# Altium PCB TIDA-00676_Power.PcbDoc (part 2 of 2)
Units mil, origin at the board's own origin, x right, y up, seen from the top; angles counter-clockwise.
Board outline 5000 x 3510 mil, 2 copper layers (Top Layer, Bottom Layer), stack 40 mil thick; 88 components, 29 nets, 205 pads, 45 vias.
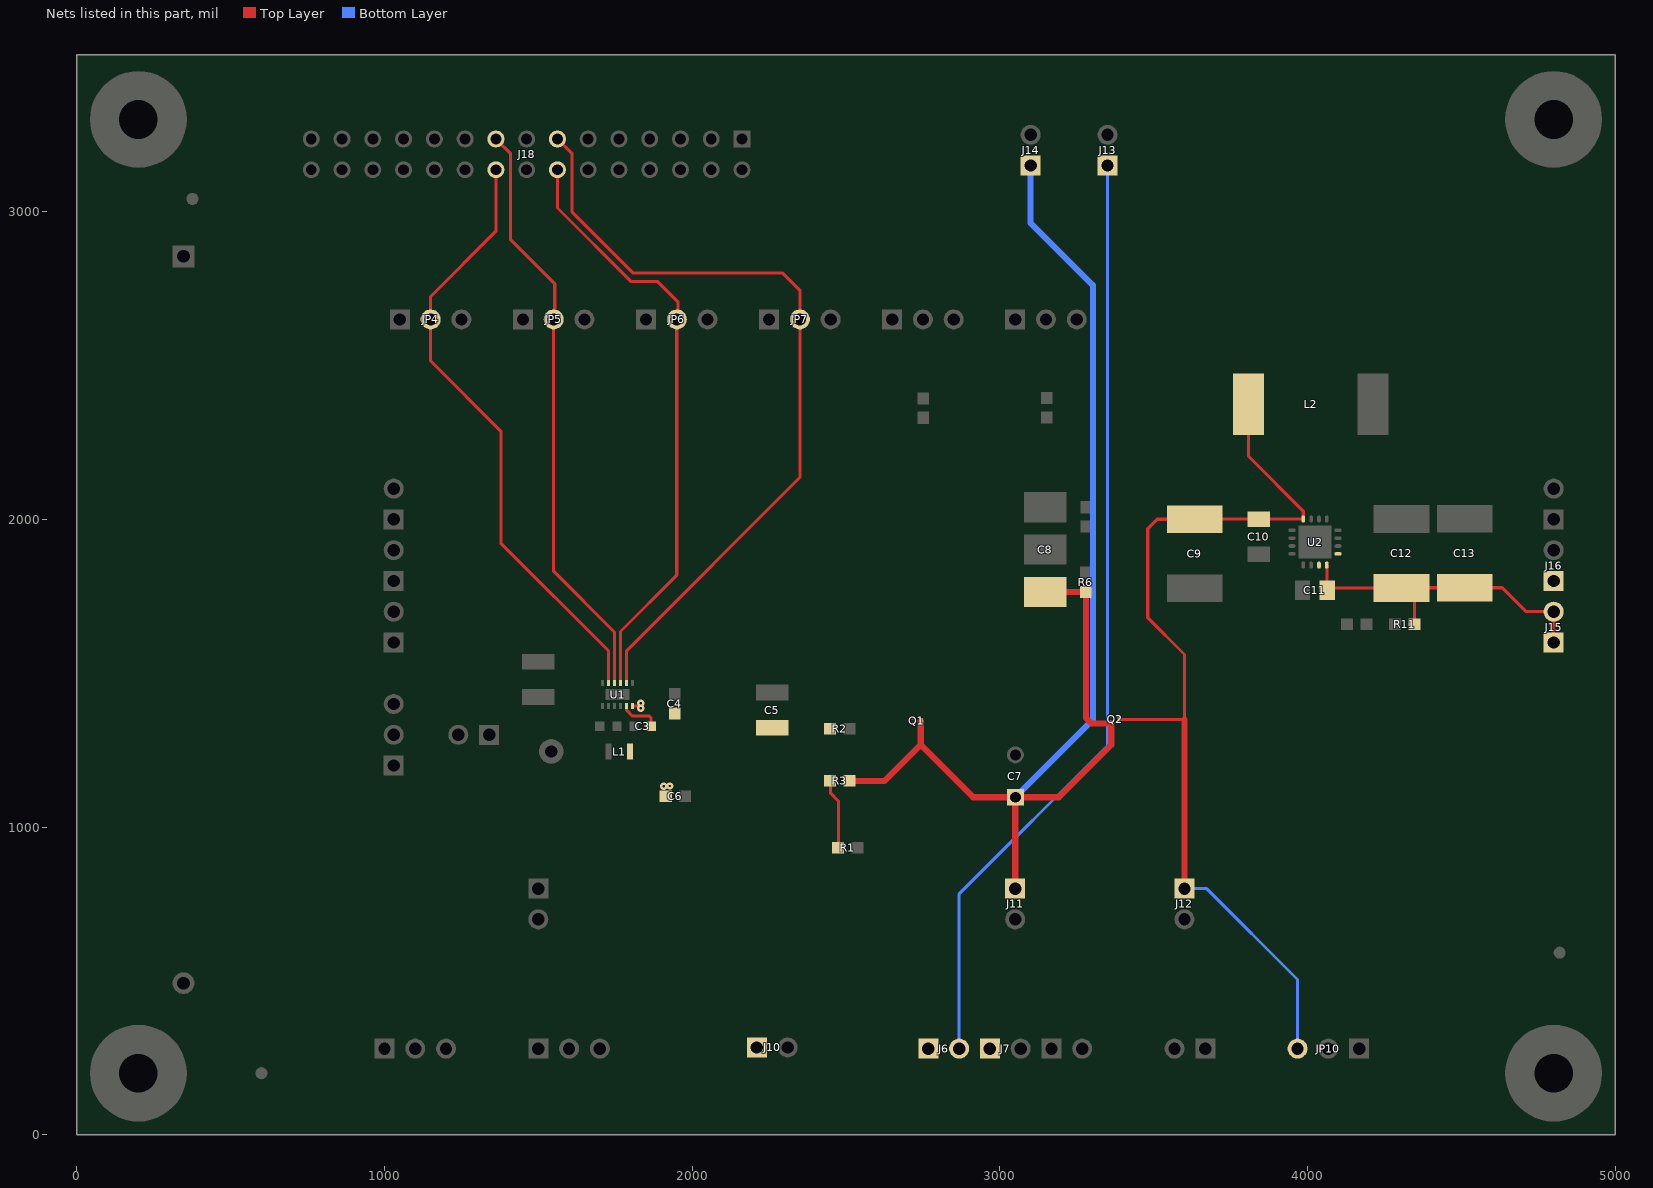
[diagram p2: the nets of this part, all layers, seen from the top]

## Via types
v1: diameter 24, hole 8, Top Layer to Bottom Layer, tented both sides, 34 vias
v2: diameter 19.68, hole 7.87, Top Layer to Bottom Layer, 5 vias
v3: diameter 19.68, hole 7.87, Top Layer to Bottom Layer, tented both sides, 4 vias
v4: diameter 34, hole 16, Top Layer to Bottom Layer, 2 vias

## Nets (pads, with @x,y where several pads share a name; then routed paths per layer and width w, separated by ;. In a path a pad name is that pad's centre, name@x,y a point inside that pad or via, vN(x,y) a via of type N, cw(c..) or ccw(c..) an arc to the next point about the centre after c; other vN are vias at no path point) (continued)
VIN_BOOST: C9.1 C10.1 J12.1 JP10.3 L2.1 Q2.3 U2.8 | length 3111.1
  Top Layer w10: Q2.3@3387.8,1350 3600,1350 3600,1561.17 3480.79,1680.37 3480.79,1969.91 3511.44,2000.56 C9.1@3633.89,2000.56 3634.18,2000.85 C10.1@3841.31,2000.85 3841.57,2001.11 U2.8@3986.05,2001.11 3986.05,2026.7 3808.56,2204.18 L2.1@3808.56,2374.34
  Top Layer w20: J12.1@3600,800 3600,1350
  Bottom Layer w10: J12.1@3600,800 3672.27,800 3967.7,504.57 JP10.3@3967.7,280
VLOAD: C6.1 J10.1 U1.6 | length 48.8
  Top Layer w10: U1.6@1806.59,1393 1822.57,1393 1832.37,1383.2 1832.37,1398.7 1832.67,1399 1832.36,1399.31 v1@1832.36,1401.86
  other v1: 1907.34,1133.06 1927.22,1133.52 1832.37,1386.2 1832.36,1402.86
VOUT_BOOST: C11.1 C12.1 C13.1 J15.1 J15.2 J16.1 R11.2 U2.1 U2.15 U2.16 | length 1088.9
  Top Layer w10: U2.16@4062.82,1851.5 4062.82,1771.09 C11.1@4063.64,1770.26 4070.66,1777.27 C12.1@4305.78,1777.27 ; R11.2@4347.25,1658.86 4347.25,1735.8 C12.1@4305.78,1777.27 ; J15.1@4800,1600 J15.2@4800,1700 4710.49,1700 4632.66,1777.83 C13.1@4511.08,1777.83 4306.34,1777.83 C12.1@4305.78,1777.27
VOUT_BUCK: C3.1 C4.1 C5.1 J6.1 J6.2 J7.1 J13.1 L1.2 R1.2 R2.1 R3.1 U1.5 | length 3434.7
  Top Layer w10: U1.5@1786.9,1393 1786.9,1379.6 1805.98,1360.52 1809.06,1360.52 ; 1809.09,1360.49 1860.44,1360.49 1866.67,1354.26 C3.1@1866.67,1327.5 ; R3.1@2448.5,1150 2450,1148.5 2450,1110 2475,1085 R1.2@2475,926.5
  Bottom Layer w10: J6.2@2867.7,280 2867.7,782.84 3350,1265.14 J13.1@3350,3150
VSEL1: J18.18 JP4.2 U1.11 | length 1995.8
  Top Layer w10: J18.18@1362.1,3136.38 1362.1,2936.54 1150,2724.44 JP4.2@1150,2650 1150,2515 1378.39,2286.61 1378.39,1922.31 1727.84,1572.86 U1.11@1727.84,1467.8
VSEL2: J18.17 JP5.2 U1.10 | length 1931
  Top Layer w10: J18.17@1362.1,3236.38 1410,3188.48 1410,2908.74 1553.3,2765.44 1553.3,2653.3 JP5.2@1550,2650 1550,1831.26 1747.53,1633.73 U1.10@1747.53,1467.8
VSEL3: J18.14 JP6.2 U1.9 | length 1958.5
  Top Layer w10: J18.14@1562.1,3136.38 1562.1,3012.11 1800.35,2773.86 1887.05,2773.86 1953.3,2707.61 1953.3,2653.3 JP6.2@1950,2650 1950,1818.7 1767.21,1635.92 U1.9@1767.21,1467.8
VSEL4: J18.13 JP7.2 U1.8 | length 2613.3
  Top Layer w10: J18.13@1562.1,3236.38 1610,3188.48 1610,2998.34 1808.12,2800.22 2294.78,2800.22 2350,2745 JP7.2@2350,2650 2350,2135.93 1786.9,1572.83 U1.8@1786.9,1467.8
VSUPER-CAP: C7.1 C8.1 J11.1 J14.1 Q1.3 Q2.2 R3.2 R6.2 | length 4356.7
  Top Layer w20: R3.2@2511.5,1150 2625.44,1150 2742.8,1267.36 ; Q1.3@2742.8,1345 2742.8,1267.36 ; J11.1@3050,800 3050,1096.46 C7.1@3050.43,1096.89 ; C8.1@3148.12,1764.3 3148.35,1764.07 R6.2@3279.85,1764.07 3279.85,1355.41 3298.92,1336.34 3362.2,1336.34 3362.2,1266.81 3192.28,1096.89 C7.1@3050.43,1096.89 ; 2742.8,1267.36 2913.26,1096.89 C7.1@3050.43,1096.89
  Bottom Layer w20: C7.1@3050.43,1096.89 3302.48,1348.94 3302.48,2760.86 3100,2963.35 J14.1@3100,3150
pads on no net: FID1.1 FID2.1 FID3.1 H1.1 H2.1 H3.1 H4.1 H5.0 H6.0 H7.0 H8.0 J18.1 J18.2 J18.3 J18.5 J18.7 J18.9 J18.10 J18.21 J18.22 J18.29 J18.30 LBL1.0 SH-JP1.0 SH-JP2.0 SH-JP3.0 SH-JP4.0 SH-JP5.0 SH-JP6.0 SH-JP7.0 SH-JP8.0 SH-JP9.0 SH-JP10.0 SH-JP11.0 U2.2 U2.9 U2.12

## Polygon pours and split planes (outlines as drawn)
GND on Bottom Layer "GND-Flood_BOT" (solid, remove dead copper, pour order 30): 50,3450 4948.63,3450 4948.63,50 50,50
VLOAD on Bottom Layer "Bottom Layer-No Net" (solid, pour order 29): 1817.38,1408.72 1817.38,1195.81 1898.86,1114.34 1934.51,1114.34 1945,1124.83 1945,1335 1945,1340 1865,1420 1860.42,1424.58 1830,1424.58 1820.45,1424.58 1816.43,1420.56
VIN_BOOST on Top Layer "Top Layer-No Net 1" (solid, remove dead copper, pour order 18): 3381.98,1330.78 3399.16,1313.6 3491.18,1313.6 3515.71,1313.6 3555.8,1273.51 3555.8,810.65 3555.8,757.37 3564.76,748.41 3565.29,747.88 3627.01,747.88 3645.73,747.88 3652.06,754.21 3652.06,1663.31 3620.45,1694.92 3545.5,1694.92 3509.01,1731.41 3509.01,1896.78 3545.5,1933.28 3652.06,1933.28 3854.66,1933.28 3891.93,1970.55 3908.99,1987.61 3989.39,1987.61 3997.02,1995.24 3997.02,2490.67 3981.39,2506.31 3755.29,2506.31 3644.2,2506.31 3528.2,2390.31 3440.71,2302.82 3440.71,2006.92 3440.71,1441.06 3388.32,1388.67 3381.98,1382.33
VOUT_BOOST on Top Layer "Top Layer-No Net" (solid, remove dead copper, pour order 16): 4026,1856.58 4026,1727.63 4031.35,1722.28 4038.16,1715.46 4155.92,1715.46 4483.87,1715.46 4627.77,1571.56 4673.54,1525.79 4803.21,1525.79 4853.33,1525.79 4864.23,1536.69 4881.66,1554.13 4881.66,1589 4881.66,1819.43 4844.81,1856.29 4698.06,1856.29 4661.24,1893.12 4087.54,1893.12 4087.54,1872.71 4078.19,1863.36 4032.79,1863.36
GND on Top Layer "GND-Flood_TOP" (solid, remove dead copper, pour order 28): 50,3450 4948.63,3450 4948.63,50 50,50
NetC8_3 on Top Layer "Top Layer-NetC8_3" (solid, pour order 19): 3078.76,1851.88 3105.14,1825.51 3234.91,1825.51 3252.37,1808.05 3301.47,1808.05 3302.34,1807.18 3313.72,1818.57 3313.72,1984.29 3302.02,1995.99 3258.81,1995.81 3235.61,1971.47 3096.64,1971.47 3078.76,1953.6
VSUPER-CAP on Top Layer "Top Layer-VSUPER_CAP" (solid, pour order 22): 2490.14,1104.93 2552.84,1042.24 3283.05,1042.24 3366.97,1126.16 3366.97,1345.93 3347.64,1345.88 3336.73,1357.21 3336.73,1783.26 3329.17,1789.13 3245.64,1789.13 3218.35,1814.73 3077.32,1814.74 3009.36,1748.9 3008.62,1628.1 2732.29,1350.12 2732.3,1277.68 2683.66,1229.03 2506.45,1229.03 2490.14,1212.72
VLOAD on Top Layer "Keep-Out Layer-VLOAD" (solid, pour order 17): 1816.34,1402.79 1827.85,1414.29 1837.35,1414.29 1845.05,1406.59 1845.05,1378.77 1840.33,1374.04 1838.91,1372.62 1833.39,1372.62 1825.56,1372.62 1818.68,1379.51 1815.03,1383.15 1801.79,1383.15 1801.79,1402.79
NetQ1_2 on Top Layer "Top Layer-NetQ1_2" (solid, pour order 20): 2490.59,1251.96 2502.91,1239.64 2674.66,1239.64 2725.7,1290.68 2725.66,1341.11 2704.84,1341.11 2697.63,1345.65 2494.14,1345.63 2494.14,1345.38 2490.59,1341.83
Q2_CTRL on Top Layer "Top Layer-Net_Q2_CTRL" (solid, pour order 23): 3367.31,1353.88 3372.13,1358.7 3372.13,1406.9 3352.68,1406.9 3352.16,1407.41 3352.16,1358.53 3356.81,1353.88
Q1_CTRL on Top Layer "Top Layer-Net_Q1_CTRL" (solid, pour order 21): 2722.33,1348.72 2722.33,1355.1 2748.09,1380.86 2734.46,1394.5 2707.28,1367.32 2707.28,1351.43 2710.06,1348.66 2722.27,1348.66
VBAT on Top Layer "Top Layer-VBAT" (solid, pour order 27): 1075,1355 1100,1380 1100,1830 1080,1850 820,1850 700,1970 700,2826.45 571.45,2955 271.29,2955 150,2833.7 150,1715 510,1355
VIN on Top Layer "Top Layer-VIN" (solid, pour order 26): 1305,1240 1305,1246.4 1286.4,1265 1286.4,1359.7 1286.4,1406.4 1340,1460 1600,1460 1620,1460 1670,1410 1673.22,1406.78 1705.07,1406.78 1713.08,1406.78 1715,1404.86 1715,1370 1715,1295 1710,1290 1675,1255 1495,1255 1480,1240
VLOAD on Top Layer "Top Layer-VLOAD" (solid, pour order 25): 2252.77,233.03 2224.74,205 1946.77,205 1921.3,230.47 1921.3,681.01 1780,822.31 1780,1130 1804.43,1154.43 1930.57,1154.43 1947.67,1137.33 1947.67,987.33 2252.77,682.23
VOUT_BUCK on Top Layer "Top Layer-VOUT_BUCK" (solid, pour order 24): 1850.83,1388.5 1850.83,1376.72 1797.06,1376.72 1791.89,1381.89 1791.89,1402.31 1781.93,1402.31 1781.93,1377.86 1806.46,1353.33 1827.44,1353.33 1831.3,1349.47 1831.3,1296.3 1825,1290 1785,1290 1780,1285 1780,1210 1798.87,1191.13 2073.87,1191.13 2206.37,1058.63 2206.37,881.83 2382.25,705.94 2382.25,504.82 2675.71,211.36 2997.75,211.36 3012.86,226.47 3012.86,440.85 2593.59,860.12 2536.43,860.12 2505.81,890.74 2505.81,1069.71 2475,1105 2475,1340 2420,1395 1851.89,1395

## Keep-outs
Keep-Out Layer:
  lines w10: -5,0 ccw(c0,0) 0,-5 ; -5,0 ccw(c0,0) 0,-5 ; -5,0 -5,3510 ; -5,3510 cw(c0,3510) 0,3515 ; -5,3510 cw(c0,3510) 0,3515 ; 0,-5 5000,-5 ; 0,3515 5000,3515 ; 5000,-5 ccw(c5000,0) 5005,0 ; 5000,-5 ccw(c5000,0) 5005,0 ; 5000,3515 cw(c5000,3510) 5005,3510 ; 5000,3515 cw(c5000,3510) 5005,3510 ; 5005,0 5005,3510
  text ".Layer_Name" at 577,-858.49 h60

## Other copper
Top Layer:
  text ".Layer_Name" at 577,-858.49 h60
Bottom Layer:
  text ".Layer_Name" at 577,-858.49 h60

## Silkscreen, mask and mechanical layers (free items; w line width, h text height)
Top Overlay:
  circle w10: c1970.69,1611.9 r5.1
  lines w10: 1200,1230 1360,1230 ; 1345,1220 1360,1230 ; 1345,1240 1360,1230 ; 1946.21,1592.35 2076.21,1592.35 2076.21,1685.27 1946.21,1685.27 1946.21,1592.35
  text "ADC1" at 3025,3005 h40
  text "ADC0" at 3280,3000 h40
  text ".PRJ_Title" at 3615,2968.1 h60
  text ".PCB_Rev" at 3852.96,2864.64 h60
  text "REV." at 3618.91,2861.81 h60
  text "LOW" at 3209.97,2537.46 h40
  text "LOW" at 1607.17,2534.07 h40
  text "LOW" at 2004.48,2534.07 h40
  text "HIGH" at 1364.57,2532.9 h40
  text "LOW" at 1204.01,2531.72 h40
  text "HIGH" at 956.72,2530.55 h40
  text "HIGH" at 1764.22,2530.55 h40
  text "LOW" at 2402.95,2530.55 h40
  text "HIGH" at 2982.68,2531.47 h40
  text "HIGH" at 2560,2530 h40
  text "LOW" at 2815,2530 h40
  text "HIGH" at 2161.52,2528.21 h40
  text "VSEL2" at 1458.33,2475.47 h40
  text "VSEL1" at 1064.55,2473.12 h40
  text "VSEL3" at 1863.84,2471.95 h40
  text "VSEL4" at 2265.82,2470.77 h40
  text "Q1 CTRL" at 2640,2470 h40
  text "Q2 CTRL" at 3034.52,2469.66 h40
  text "GND" at 4731.03,1969.15 h40 r90
  text "GND" at 1160,1945 h40 r90
  text "U1" at 1992.72,1626.73 h40
  text "VBOOST" at 4731.03,1579.15 h40 r90
  text "RF AMP SUPPLY" at 4664.28,1575.97 h40 r90
  text "VIN_BAT" at 1170,1560 h40 r90
  text "1" at 1961.52,1530.9 h39.37
  text "VIN_BAT" at 699.85,1396.07 h40
  text "VIN" at 845,1280 h40
  text "3V3_REF" at 699.85,1186.07 h40
  text "I_IN" at 1215,1158 h40
  text "TP" at 1465,595 h40
  text "TP" at 3020,595 h40
  text "TP" at 3565,595 h40
  text "VIN_BUCK" at 1445,540 h40
  text "VSUPERCAP" at 2870,540 h40
  text "VIN_BOOST" at 3470,540 h40
  text "CTRL" at 1565,425 h40
  text "METROLOGY" at 2819.7,418.1 h40
  text "TPS62740" at 954.8,411.8 h40
  text "TPS61291" at 3926.38,408.78 h40
  text "VLOAD" at 2163.6,359 h40
  text "L_ON" at 1437.12,354.36 h40
  text "L_OFF" at 1661.82,354.35 h40
  text "VOUT_BUCK" at 2669.1,350.9 h40
  text "ON" at 945.3,350 h40
  text "EN" at 1055.3,350 h40
  text "OFF" at 1165.3,350 h40
  text "OFF" at 4124.57,347.99 h40
  text "ON" at 3924.71,346.33 h40
  text "GND" at 3117.7,345 h40
  text "GND" at 3507.7,345 h40
  text "PG" at 3652.7,345 h40
  text "EN" at 4028.81,344.66 h40
  text ".Layer_Name" at 577,-858.49 h60
Bottom Overlay:
  text ".Layer_Name" at 577,-858.49 h60
Top Paste:
  text ".Layer_Name" at 577,-858.49 h60
Bottom Paste:
  text ".Layer_Name" at 577,-858.49 h60
Top Solder:
  text ".Layer_Name" at 577,-858.49 h60
  text ".Layer_Name" at 577,-858.49 h60
Bottom Solder:
  text ".Layer_Name" at 577,-858.49 h60
Drill Guide:
  text ".Layer_Name" at 577,-858.49 h60
M1 Board Outline:
  the board outline again, w10
  text ".Layer_Name" at 577,-858.49 h60
M2 Board Dimensions:
  rectangle: -0.5,-285.5 124.5,-160.5
  rectangle: 124.5,-410.5 499.5,-285.5
  lines w7: -0.5,-285.5 999.5,-285.5 ; 124.5,-410.5 124.5,-160.5 ; 249.5,-410.5 249.5,-160.5 ; 499.5,-410.5 499.5,-160.5 ; 749.5,-410.5 749.5,-160.5 ; -0.5,-410.5 999.5,-410.5 999.5,-160.5 -0.5,-160.5 -0.5,-410.5
  lines w10: -0.5,-475.5 -0.5,-455.5 ; 59.5,-485.5 -0.5,-465.5 ; 59.5,-445.5 -0.5,-465.5 ; 223.58,-465.5 -0.5,-465.5 ; 775.42,-465.5 999.5,-465.5 ; 939.5,-485.5 999.5,-465.5 ; 939.5,-445.5 999.5,-465.5 ; 999.5,-475.5 999.5,-455.5
  text "1000 (mil)" at 233.58,-501.49 h60
  text ".Layer_Name" at 577,-858.49 h60
M3 3D STEP Top:
  text ".Layer_Name" at 577,-858.49 h60
M4 3D STEP Bottom:
  text ".Layer_Name" at 577,-858.49 h60
M5 Assembly Top:
  lines w10: -292,-930.17 6308,-930.17 ; -292,-726.83 6310,-726.83 ; -292,-523.5 -292,-1133.5 3713,-1133.5 6310,-1133.5 6310,-523.5 -291.5,-523.5 -291.5,-1133.5 1284,-1133.5 ; 2173,-1133.5 2173,-523.5 ; 3440,-726.83 3440,-523.5 ; 4280,-726.83 4280,-523.5 ; 4902,-1140 4902,-937.17
  text "COMPONENTS MARKED 'DNP' SHOULD NOT BE POPULATED." at 1153.5,-318.5 h60
  text "ASSEMBLY VARIANT:" at 1153,-434 h60
  text ".VariantName" at 2189,-434 h60
  text "PCB VIEWED FROM TOP SIDE" at -228.5,-655.67 h60
  text "BOARD #:" at 2248,-655.67 h60
  text ".PRJ_Number" at 2793.5,-655.67 h60
  text "REV:" at 3638,-655.67 h60
  text ".PCB_Rev" at 3929.5,-655.67 h60
  text "SVN REV:" at 4476,-655.67 h60
  text ".VersionControl_RevNumber" at 4982,-655.67 h60
  text "IGNORE ->" at -228.5,-858.49 h60
  text "PLOT NAME =" at -228.5,-1064.34 h60
  text ".plot_File_Name" at 577,-1064.34 h60
  text "GENERATED    :" at 2250,-1064.34 h60
  text ".Print_Date" at 3119.5,-1064.34 h60
  text ".Print_Time" at 3848.5,-1064.34 h60
  text "TEXAS INSTRUMENTS" at 5113,-1064.34 h60
M6 Assembly Bottom:
  lines w10: -292.5,-727.33 6309.5,-727.33 ; -290.5,-930.67 6309.5,-930.67 ; 1115.5,-1140.5 1115.5,-937.67 ; 1737.5,-727.33 1737.5,-524 ; 2577.5,-727.33 2577.5,-524 ; 3844.5,-1134 3844.5,-524 ; 4733.5,-1134 6309,-1134 6309,-524 -292.5,-524 -292.5,-1134 2304.5,-1134 6309.5,-1134 6309.5,-524
  text "COMPONENTS MARKED 'DNP' SHOULD NOT BE POPULATED." at 6102,-318 h60
  text ".VariantName" at 5058,-434 h60
  text "ASSEMBLY VARIANT:" at 6097,-434 h60
  text ".VersionControl_RevNumber" at 1035.5,-656.17 h60
  text "SVN REV:" at 1541.5,-656.17 h60
  text ".PCB_Rev" at 2088,-656.17 h60
  text "REV:" at 2379.5,-656.17 h60
  text ".PRJ_Number" at 3224,-656.17 h60
  text "BOARD #:" at 3769.5,-656.17 h60
  text "PCB VIEWED FROM BOTTOM SIDE" at 6246,-656.17 h60
  text "IGNORE ->" at 2547.85,-858.49 h60
  text "TEXAS INSTRUMENTS" at 904.5,-1064.84 h60
  text ".Print_Time" at 2169,-1064.84 h60
  text ".Print_Date" at 2898,-1064.84 h60
  text "GENERATED    :" at 3767.5,-1064.84 h60
  text ".plot_File_Name" at 5440.5,-1064.84 h60
  text "PLOT NAME =" at 6246,-1064.84 h60
M9 Title Sheet:
  drawing of 57 lines, arcs and shapes, not listed
  text "1" at 739.84,8036.5 h70
  text "2" at 3235.5,8036.5 h70
  text "3" at 5724.84,8036.5 h70
  text "4" at 8231.51,8036.5 h70
  text "5" at 10730.5,8036.5 h70
  text "6" at 13235.5,8036.5 h70
  text "A" at -416.5,6893.5 h70
  text "A" at 14383.5,6893.5 h70
  text "B" at -416.5,4513.5 h70
  text "B" at 14383.5,4513.5 h70
  text "C" at -416.5,2138.5 h70
  text "C" at 14383.5,2138.5 h70
  text "PROJECT TITLE:" at 11343.5,277.5 h45
  text ".PRJ_Title" at 11393.5,144.17 h70
  text "DESIGNED FOR:" at 11343.5,-23.5 h45
  text ".PRJ_Customer" at 11393.5,-163.5 h70
  text "D" at -416.5,-231.5 h70
  text "D" at 14383.5,-231.5 h70
  text "FILE NAME:" at 11343.5,-323.5 h45
  text ".PCB_File_Name_No_Path" at 11393.5,-443.5 h70
  text "Texas Instruments (TI) and/or its licensors do not warrant the accuracy or completeness of this specification" at 6374,-605.34 h45
  text "ENGINEER:" at 11343.5,-613.5 h45
  text "LAYOUT BY:" at 12848.5,-613.5 h45
  text "or any information contained therein. TI and/or its licensors do not warrant that this design will meet" at 6329.01,-718 h45
  text ".PRJ_Engineer" at 11393.5,-768.49 h70
  text ".PCB_Layout" at 12899,-768.49 h70
  text "the specifications, will be suitable for your application or fit for any particular purpose, or will operate in" at 6329.01,-830.67 h45
  text ".Layer_Name" at 577,-858.49 h60
  text "ALTIUM DESIGNER VERSION:" at 12848.5,-923.5 h45
  text "an implementation. TI and/or its licensors do not warrant that the design is production worthy. You should" at 6329.01,-943.33 h45
  text "completely validate and test your design implementation to confirm the system functionality for your application." at 6374,-1056 h45
  text ".print_Scale" at 11393.5,-1056.83 h70
  text ".Application_BuildNumber" at 12899,-1056.83 h70
  text "1" at 739.84,-1263.5 h70
  text "2" at 3235.5,-1263.5 h70
  text "3" at 5724.84,-1263.5 h70
  text "4" at 8231.51,-1263.5 h70
  text "5" at 10730.5,-1263.5 h70
  text "6" at 13235.5,-1263.5 h70
M10 Fab Notes:
  drawing of 185 lines, arcs and shapes, not listed
  text "DESIGN INFORMATION" at 12376.42,5919.2 h60
  text "MIN. TRACK WIDTH:" at 11731.86,5739.2 h60
  text "8" at 12828.1,5739.2 h60
  text "MIL" at 12982.86,5739.2 h60
  text "7.4" at 12764.81,5618.63 h60
  text "MIN. CLEARANCE:" at 11731.86,5607.2 h60
  text "MIL" at 12982.86,5607.2 h60
  text "19.685" at 12610.55,5479.79 h60
  text "MIN. VIA PAD SIZE:" at 11731.86,5475.2 h60
  text "MIL" at 12982.86,5475.2 h60
  text "EXTERNAL" at 13186.46,5340.95 h60
  text "0.15mm (5.9 MIL)" at 12426.86,5333.49 h60
  text "MINIMUM ANNULAR RING" at 11402.63,5329.2 h60
  text "PER" at 11602.63,5211.2 h60
  text "IPC-D-275 CLASS 2 LEVEL C" at 11822.63,5211.2 h60
  text "MIL, HOLES" at 13310.86,5098.91 h60
  text "+/-" at 12918.4,5098.2 h60
  text "+/-" at 13772.4,5098.2 h60
  text "REGISTRATION TOLERANCES:" at 11402.63,5093.2 h60
  text "METAL" at 12602.4,5093.2 h60
  text "5" at 13178.6,5093.2 h60
  text "3" at 14011.6,5093.2 h60
  text "MIL" at 14127.86,5093.2 h60
  text "MATERIAL:" at 11327.86,4883.74 h60
  text "FR-4 High Tg" at 12314.3,4743.41 h60
  text "FR-408" at 11748.86,4734.84 h60
  text "X" at 12160.86,4734.84 h60
  text "OTHER" at 13236.86,4734.84 h60
  text "62 MIL (1.6mm) +/-10%" at 12068.96,4572.12 h60
  text "40 MIL+/-10%" at 13641.9,4568.96 h60
  text "THICKNESS:" at 11402.63,4567.84 h60
  text "OTHER" at 13353.86,4567.84 h60
  text "X" at 13231.46,4562.7 h60
  text "TOLERANCE:" at 11402.63,4409.84 h60
  text "X" at 12241.93,4409.84 h60
  text "ANSI IPC-6012 TYPE 3 CLASS 2" at 12428.88,4409.84 h60
  text "OTHER +/-" at 12428.86,4253.84 h60
  text "BOW & TWIST:" at 11402.63,4096.84 h60
  text "X" at 12241.93,4096.84 h60
  text "ANSI IPC-6012 TYPE 3 CLASS 2" at 12428.88,4096.84 h60
  text "OTHER +/-" at 12428.86,3938.33 h60
  text "DRILLING:" at 11327.86,3799.84 h60
  text "REFERENCE:" at 11402.63,3682.84 h60
  text "X" at 12050.86,3682.84 h60
  text "AS SHOWN" at 12237.86,3682.84 h60
  text "X" at 12951.86,3682.84 h60
  text "NC_DRILL FILES" at 13088.86,3682.84 h60
  text "PTH MIN COPPER THICKNESS:" at 11402.63,3524.84 h60
  text "X" at 12752.86,3524.84 h60
  text "1MIL" at 12889.86,3524.84 h60
  text "OTHER" at 13386.86,3524.84 h60
  text "BOARD FINISH:" at 11327.86,3365.84 h60
  text "SILKSCREEN:" at 11483.08,3247.84 h60
  text "X" at 12431.86,3247.84 h60
  text "TOP" at 12557.86,3247.84 h60
  text "BOTTOM" at 13068.86,3247.84 h60
  text "SILKSCREEN COLOR:" at 11483.08,3080.84 h60
  text "X" at 12430.82,3080.84 h60
  text "WHITE" at 12557.86,3080.84 h60
  text "OTHER" at 13068.86,3080.84 h60
  text "SOLDER RESIST COLOR:" at 11483.08,2910.84 h60
  text "X" at 12050.82,2751.64 h60
  text "GREEN" at 12177.86,2751.64 h60
  text "BLUE" at 12768.86,2751.64 h60
  text "OTHER" at 13306.86,2751.64 h60
  text "IMMERSION GOLD (ENIG)" at 12388.86,2563.12 h60
  text "ENEPIG" at 13726.4,2559.84 h60
  text "SURFACE FINISH:" at 11327.86,2558.84 h60
  text "X" at 12201.91,2558.84 h60
  text "IMM. TIN/SILVER OR EQUIV" at 11657.4,2401.84 h60
  text "OTHER" at 13088.86,2401.84 h60
  text "ARRAY/PANEL:" at 11327.86,2222.84 h60
  text "CUT AND TRIM PER MECH LAYER 1" at 12388.86,2218.55 h60
  text "N.C. ROUTE" at 12388.86,2066.84 h60
  text "X" at 13067.86,2066.84 h60
  text "V. SCORE" at 13254.86,2066.84 h60
  text "CERTIFICATION:" at 11327.86,1929.84 h60
  text "MATERIALS AND WORKMANSHIP FOR ALL PCBS" at 12052.86,1929.84 h60
  text "TO MEET OR EXCEED THE REQUIREMENTS OF:" at 12052.86,1831.84 h60
  text "X" at 11679.36,1695.33 h60
  text "ANSI IPC-A-600F CLASS ->" at 11818.36,1695.33 h60
  text "X" at 13457.42,1695.33 h60
  text "2" at 13576.36,1695.34 h60
  text "1" at 13261.36,1693.84 h60
  text "3" at 13930.36,1693.84 h60
  text "X" at 11681.42,1535.84 h60
  text "UL 94V-0" at 11818.36,1535.84 h60
  text "X" at 12493.42,1535.84 h60
  text "RoHS" at 12630.36,1535.84 h60
  text "OTHER" at 13274.76,1535.84 h60
  text "PER ORDER" at 13671.82,1535.84 h60
  text "ADDITIONAL REQUIREMENTS:" at 11327.86,1394.84 h60
  text "MICROSECTION:" at 11402.63,1279.84 h60
  text "YES" at 12308.36,1279.84 h60
  text "REQUIRED" at 13169.86,1123.69 h60
  text "BARE BOARD ELEC. TEST:" at 11402.63,1120.84 h60
  text "NONE" at 12708.36,1120.84 h60
  text "X" at 13042.86,1120.84 h60
  text "PER ORDER" at 13761.86,1120.84 h60
  text "MANUFACTURER'S UL:" at 11402.63,963.84 h60
  text "RAIL" at 12568.36,959.55 h60
  text "METAL" at 13060.17,959.55 h60
  text "SILK" at 13571.86,959.55 h60
  text "X" at 13435.4,959.2 h60
  text ".Layer_Name" at 577,-858.49 h60
M11 Gerber Information:
  lines w10: -292,-930.17 6308,-930.17 ; -292,-726.83 6310,-726.83 ; -292,-523.5 -292,-1133.5 3713,-1133.5 6310,-1133.5 6310,-523.5 -291.5,-523.5 -291.5,-1133.5 1284,-1133.5 ; 2173,-1133.5 2173,-523.5 ; 3440,-726.83 3440,-523.5 ; 4280,-726.83 4280,-523.5 ; 4902,-1140 4902,-937.17
  text "ALL ARTWORK VIEWED FROM TOP SIDE" at -228.5,-655.67 h60
  text "BOARD #:" at 2248,-655.67 h60
  text ".PRJ_Number" at 2793.5,-655.67 h60
  text "REV:" at 3638,-655.67 h60
  text ".PCB_Rev" at 3929.5,-655.67 h60
  text "SVN REV:" at 4476,-655.67 h60
  text ".VersionControl_RevNumber" at 4982,-655.67 h60
  text "LAYER NAME =" at -228.5,-858.49 h60
  text "PLOT NAME =" at -228.5,-1064.34 h60
  text ".plot_File_Name" at 577,-1064.34 h60
  text "GENERATED    :" at 2250,-1064.34 h60
  text ".Print_Date" at 3119.5,-1064.34 h60
  text ".Print_Time" at 3848.5,-1064.34 h60
  text "TEXAS INSTRUMENTS" at 5113,-1064.34 h60
M12 Stackup:
  drawing of 191 lines, arcs and shapes, not listed
  text "Layer" at 9789.31,7825.77 h60
  text "Name" at 10199.22,7825.77 h60
  text "Material" at 11128.97,7825.77 h60
  text "Thickness" at 11988.73,7825.77 h60
  text "Constant" at 12638.57,7825.77 h60
  text "Board Layer Stack" at 13208.43,7825.77 h60
  text "1" at 9789.31,7705.77 h60
  text "Top Overlay" at 10199.22,7705.77 h60
  text "2" at 9789.31,7585.77 h60
  text "Top Solder" at 10199.22,7585.77 h60
  text "Solder Resist" at 11128.97,7585.77 h60
  text "0.40mil" at 11988.73,7585.77 h60
  text "3.5" at 12638.57,7585.77 h60
  text "3" at 9789.31,7465.77 h60
  text "Top Layer" at 10199.22,7465.77 h60
  text "Copper" at 11128.97,7465.77 h60
  text "1.40mil" at 11988.73,7465.77 h60
  text "4" at 9789.31,7345.77 h60
  text "Dielectric1" at 10199.22,7345.77 h60
  text "FR-4" at 11128.97,7345.77 h60
  text "37.20mil" at 11988.73,7345.77 h60
  text "4.8" at 12638.57,7345.77 h60
  text "5" at 9789.31,7225.77 h60
  text "Bottom Layer" at 10199.22,7225.77 h60
  text "Copper" at 11128.97,7225.77 h60
  text "1.40mil" at 11988.73,7225.77 h60
  text "6" at 9789.31,7105.77 h60
  text "Bottom Solder" at 10199.22,7105.77 h60
  text "Solder Resist" at 11128.97,7105.77 h60
  text "0.40mil" at 11988.73,7105.77 h60
  text "3.5" at 12638.57,7105.77 h60
  text "7" at 9789.31,6985.77 h60
  text "Bottom Overlay" at 10199.22,6985.77 h60
  text ".Layer_Name" at 577,-858.49 h60
M13 Component Bodies Top:
  text ".Layer_Name" at 577,-858.49 h60
M14 Component Bodies Bottom:
  text ".Layer_Name" at 577,-858.49 h60
M15 Courtyards Top:
  text ".Layer_Name" at 577,-858.49 h60
M16 Courtyards Bottom:
  text ".Layer_Name" at 577,-858.49 h60
Drill Drawing:
  circle w1: c5327.89,3246.34 r24.89
  circle w1: c5327.89,2499.74 r14.93
  circle w1: c5327.89,2499.74 r24.89
  lines w1: 5303.01,2337.97 5315.45,2337.97 5315.45,2325.53 5340.34,2325.53 5340.34,2337.97 5352.78,2337.97 5352.78,2362.86 5340.34,2362.86 5340.34,2375.3 5315.45,2375.3 5315.45,2362.86 5303.01,2362.86 5303.01,2337.97 ; 5303.01,2673.94 5352.78,2673.94 5327.89,2624.17 5303.01,2673.94 ; 5303.01,2773.49 5352.78,2773.49 5352.78,2823.26 5303.01,2823.26 5303.01,2773.49 ; 5303.01,2947.7 5327.89,2922.81 5352.78,2947.7 5327.89,2972.58 5303.01,2947.7 ; 5303.01,3072.13 5352.78,3072.13 5352.78,3121.9 5303.01,3121.9 5303.01,3072.13 ; 5312.96,2783.45 5342.83,2783.45 5342.83,2813.31 5312.96,2813.31 5312.96,2783.45
  lines w12: 5235.18,2280.73 7353.2,2280.73 ; 5235.18,3325.97 7353.2,3325.97 ; 5605.54,2131.41 5605.54,3475.29 ; 5962.54,2131.41 5962.54,3475.29 ; 6624.1,2131.41 6624.1,3475.29 ; 6908.24,2131.41 6908.24,3475.29 ; 5235.18,2131.41 7353.2,2131.41 7353.2,3475.29 5235.18,3475.29 5235.18,2131.41
  text "Symbol" at 5324.77,3370.77 h72
  text "Quantity" at 5650.34,3370.77 h72
  text "Finished Hole Size" at 6007.34,3370.77 h72
  text "Plated" at 6668.9,3370.77 h72
  text "Hole Type" at 6953.04,3370.77 h72
  text "9" at 5650.34,3221.45 h60
  text "7.87mil (0.200mm)" at 6007.34,3221.45 h60
  text "PTH" at 6668.9,3221.45 h60
  text "Round" at 6953.04,3221.45 h60
  text "34" at 5650.34,3072.13 h60
  text "8.00mil (0.203mm)" at 6007.34,3072.13 h60
  text "PTH" at 6668.9,3072.13 h60
  text "Round" at 6953.04,3072.13 h60
  text "2" at 5650.34,2922.81 h60
  text "16.00mil (0.406mm)" at 6007.34,2922.81 h60
  text "PTH" at 6668.9,2922.81 h60
  text "Round" at 6953.04,2922.81 h60
  text "32" at 5650.34,2773.49 h60
  text "35.43mil (0.900mm)" at 6007.34,2773.49 h60
  text "PTH" at 6668.9,2773.49 h60
  text "Round" at 6953.04,2773.49 h60
  text "65" at 5650.34,2624.17 h60
  text "40.00mil (1.016mm)" at 6007.34,2624.17 h60
  text "PTH" at 6668.9,2624.17 h60
  text "Round" at 6953.04,2624.17 h60
  text "2" at 5650.34,2474.85 h60
  text "41.34mil (1.050mm)" at 6007.34,2474.85 h60
  text "PTH" at 6668.9,2474.85 h60
  text "Round" at 6953.04,2474.85 h60
  text "4" at 5650.34,2325.53 h60
  text "125.98mil (3.200mm)" at 6007.34,2325.53 h60
  text "PTH" at 6668.9,2325.53 h60
  text "Round" at 6953.04,2325.53 h60
  text "148 Total" at 5650.34,2176.21 h60
  text ".Layer_Name" at 577,-858.49 h60

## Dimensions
0,0 to 0,3510 on M2 Board Dimensions
0,0 to 5000,0 on M2 Board Dimensions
